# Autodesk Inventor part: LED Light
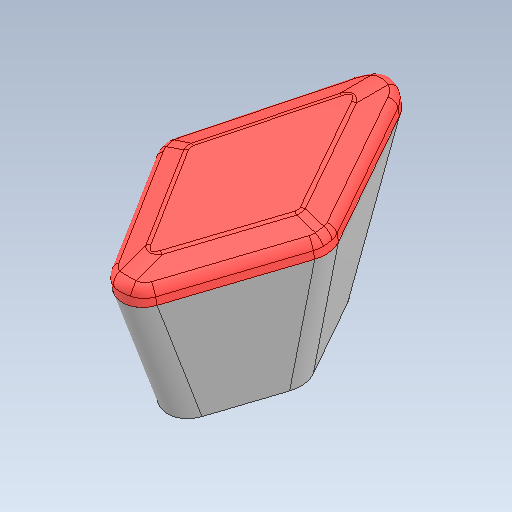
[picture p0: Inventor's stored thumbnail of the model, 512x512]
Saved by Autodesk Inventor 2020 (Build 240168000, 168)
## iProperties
Created: 2021-10
Part Number: LED Light
Material: Steel
Document SubType Name: Modeling
Designer: bruno
Density: 7.85 g/cm^3
Appearance: Par défaut
Author: bruno
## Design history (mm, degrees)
feature "Rear Light Body"
feature "Red Transparent cover"
feature "LED"
feature "Composite1"
node "Solide1"
node "Solide2"
node "Solide3"
body "Srf1"
